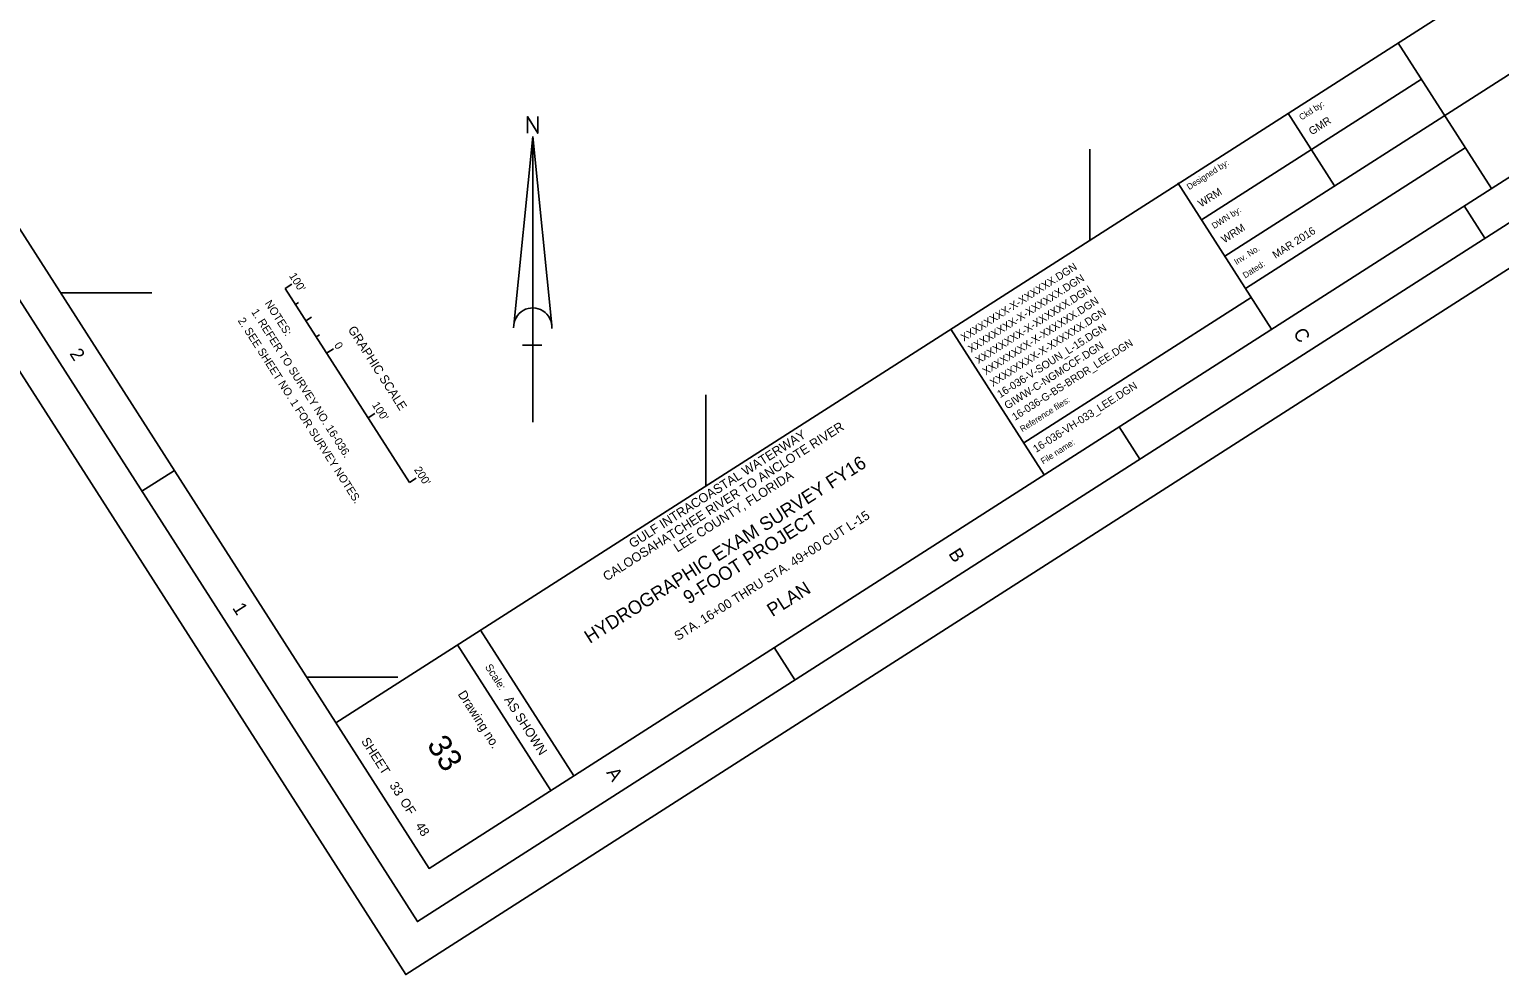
# Model space of a CAD drawing. Extents: x 582737 to 587973, y 836613 to 842151.
# Drawn here: x 584619 to 586533, y 836613 to 837843 of the extents above; entities that cross this region are included whole.
import ezdxf

# ---------------------------------------------------------------- set-up
doc = ezdxf.new("R2010")
doc.units = 0
for name, color, linetype in [('G-ANNO-NPLT', 7, 'Continuous'), ('G-ANNO-TEXT-DRWG', 7, 'Continuous'), ('G-ANNO-TEXT-PROJ', 7, 'Continuous'), ('G-ANNO-TEXT-TTLB', 7, 'Continuous'), ('G-ANNO-TTLB', 7, 'Continuous'), ('V-ANNO-NOTE', 7, 'Continuous'), ('V-ANNO-SYMB', 7, 'Continuous'), ('V-TOPO-COOR-STAT', 7, 'Continuous')]:
    doc.layers.add(name, color=color, linetype=linetype)

msp = doc.modelspace()

# ---------------------------------------------------------------- linework, layer by layer
at = {"layer": 'G-ANNO-NPLT'}
msp.add_lwpolyline([(585600.9, 842151.5), (587972.9, 838445.7), (585109.4, 836612.7), (582737.3, 840318.5)], close=True, dxfattribs=at)
msp.add_lwpolyline([(585151.5, 836639.5), (585109.4, 836612.6), (585082.5, 836654.7)], dxfattribs=at)
at = {"layer": 'G-ANNO-TTLB'}
for p, q in [((587713.5, 838665.5), (585018.4, 836940.3)), ((586175.4, 837548.1), (586899.7, 838011)), ((586400.7, 837826.1), (586522.5, 837635.9)), ((586145.3, 837595.3), (586431.4, 837778.2)), ((586257.7, 837734.5), (586318.5, 837639.6)), ((586488.5, 837689), (586202.4, 837505.9)), ((586114.4, 837643.3), (586236.4, 837452.8)), ((586514.1, 837571.2), (586487.2, 837613.3)), ((586209.8, 837494.3), (585913.9, 837304.9)), ((585819.1, 837452.9), (585940.4, 837263.4)), ((586064.9, 837283.7), (586038, 837325.8)), ((584766, 837241.8), (584808.1, 837268.8)), ((585206.8, 837061), (585328.1, 836871.4)), ((585176.8, 837041.7), (585298.1, 836852.2)), ((585615.8, 836996.2), (585588.8, 837038.3))]:
    msp.add_line(p, q, dxfattribs=at)
for points in [[(582806.4, 840303.3), (585124.5, 836681.7), (587903.9, 838460.8), (585585.7, 842082.4)], [(587834.8, 838476), (585611, 841950.2), (582915.9, 840225), (585139.7, 836750.8)]]:
    msp.add_lwpolyline(points, close=True, dxfattribs=at)
at = {"layer": 'V-ANNO-NOTE'}
for p, q in [((584952.4, 837505.9), (584961.2, 837511.5)), ((584952.4, 837505.9), (585114.1, 837253.2)), ((584965.9, 837484.8), (584969.9, 837487.4)), ((584979.4, 837463.8), (584986.5, 837468.4)), ((584992.8, 837442.7), (584996.9, 837445.3)), ((585006.3, 837421.7), (585015.1, 837427.3)), ((585006.3, 837421.7), (585015.1, 837427.3)), ((585006.3, 837421.7), (585010.5, 837424.4)), ((585060.2, 837337.4), (585069, 837343.1)), ((585114.1, 837253.2), (585122.9, 837258.8))]:
    msp.add_line(p, q, dxfattribs=at)
at = {"layer": 'V-ANNO-SYMB'}
for p, q in [((585249.9, 837458.2), (585274.6, 837703.9)), ((585274.6, 837331.6), (585274.6, 837703.9)), ((585299.3, 837458.2), (585274.6, 837703.9)), ((585286.4, 837432.1), (585261.5, 837432.1))]:
    msp.add_line(p, q, dxfattribs=at)
msp.add_lwpolyline([(585267.7, 837707.9), (585267.7, 837729.6), (585281.2, 837707.9), (585281.2, 837729.6)], dxfattribs=at)
msp.add_arc((585274.6, 837455.7), 24.8, 355.2984, 182.0673, dxfattribs=at)
at = {"layer": 'V-TOPO-COOR-STAT'}
for p, q in [((586000, 837568.7), (586000, 837687.4)), ((584660.1, 837500), (584778.9, 837500)), ((585500, 837248.6), (585500, 837367.4)), ((584980.2, 837000), (585098.9, 837000))]:
    msp.add_line(p, q, dxfattribs=at)

# ---------------------------------------------------------------- texts
at = {"layer": 'G-ANNO-TEXT-DRWG'}
for s, height, rotation, p in [('GMR', 10, 32.6232, (586288.8, 837705.1)), ('WRM', 10, 32.6232, (586144.7, 837611.1)), ('WRM', 10, 32.6232, (586174.9, 837564.4)), ('XXXXXXXX-X-XXXXXX.DGN', 10, 32.6232, (585835.9, 837436.6)), ('XXXXXXXX-X-XXXXXX.DGN', 10, 32.6232, (585845.3, 837421.9)), ('XXXXXXXX-X-XXXXXX.DGN', 10, 32.6232, (585854.8, 837407.1)), ('XXXXXXXX-X-XXXXXX.DGN', 10, 32.6232, (585864.2, 837392.4)), ('XXXXXXXX-X-XXXXXX.DGN', 10, 32.6232, (585873.7, 837377.7)), ('16-036-V-SOUN_L-15.DGN', 10, 32.6232, (585883.1, 837362.9)), ('GIWW-C-NGMCCF.DGN', 10, 32.6232, (585892.5, 837348.2)), ('16-036-VH-033_LEE.DGN', 10, 32.6232, (585929.9, 837291.7)), ('STA. 16+00 THRU STA. 49+00 CUT L-15', 12, 32.6232, (585463.7, 837046.8)), ('PLAN', 17.5, 32.6232, (585586.7, 837077.8)), ('33', 30, 302.6232, (585136, 836911.9)), (' 33          48', 12, 302.6232, (585085.3, 836862.6))]:
    msp.add_text(s, height=height, rotation=rotation, dxfattribs=at).set_placement(p)
at = {"layer": 'G-ANNO-TEXT-PROJ'}
for s, height, p in [('MAR 2016', 10, (586241.5, 837544.3)), ('16-036-G-BS-BRDR_LEE.DGN', 9.8, (585902.4, 837333.5)), ('CALOOSAHATCHEE RIVER TO ANCLOTE RIVER', 12, (585370.9, 837124.4)), ('GULF INTRACOASTAL WATERWAY', 12, (585404.7, 837167.4)), ('HYDROGRAPHIC EXAM SURVEY FY16', 17.5, (585349, 837043)), ('LEE COUNTY, FLORIDA', 12, (585462.9, 837161.9)), ('9-FOOT PROJECT', 17.5, (585477.6, 837094.2))]:
    msp.add_text(s, height=height, rotation=32.6232, dxfattribs=at).set_placement(p)
at = {"layer": 'G-ANNO-TEXT-TTLB'}
for s, height, rotation, p in [('Ckd by:', 8, 32.6232, (586275.4, 837724.5)), ('Designed by:', 8, 32.6232, (586129.2, 837633.8)), ('DWN by:', 8, 32.6232, (586161.7, 837583.1)), ('Inv. No.', 8, 32.6232, (586190.8, 837536.2)), ('Dated:', 8, 32.6232, (586202.1, 837518.7)), ('Reference files:', 8, 32.6232, (585912, 837318.6)), ('File name:', 8, 32.6232, (585939.1, 837276.7)), ('Scale:', 10, 302.6232, (585212.1, 837013.1)), ('Drawing no.', 12, 302.6232, (585176.6, 836977.7)), ('AS SHOWN', 12, 302.6232, (585237, 836970.5)), ('SHEET         OF', 12, 302.6232, (585050.8, 836916.6))]:
    msp.add_text(s, height=height, rotation=rotation, dxfattribs=at).set_placement(p)
at = {"layer": 'G-ANNO-TTLB'}
for s, p in [('C', (586263.9, 837447.6)), ('2', (584671.1, 837421)), ('B', (585815.2, 837160.6)), ('1', (584883.1, 837089.9)), ('A', (585369.9, 836875.6))]:
    msp.add_text(s, height=17.5, rotation=302.6232, dxfattribs=at).set_placement(p)
at = {"layer": 'V-ANNO-NOTE'}
for s, height, p in [("100'", 10.42, (584957, 837522.3)), ('NOTES:', 10.42, (584925.3, 837486.5)), ('1. REFER TO SURVEY NO. 16-036.', 10.416, (584907.8, 837475.3)), ('2. SEE SHEET NO. 1 FOR SURVEY NOTES.', 10.416, (584890.3, 837464)), ('GRAPHIC SCALE', 11.666, (585033.6, 837452.4)), ('0', 10.4, (585015.6, 837432)), ("100'", 10.42, (585065, 837354.3)), ("200'", 10.42, (585119.7, 837269.9))]:
    msp.add_text(s, height=height, rotation=302.6232, dxfattribs=at).set_placement(p)

doc.saveas('drawing.dxf')
